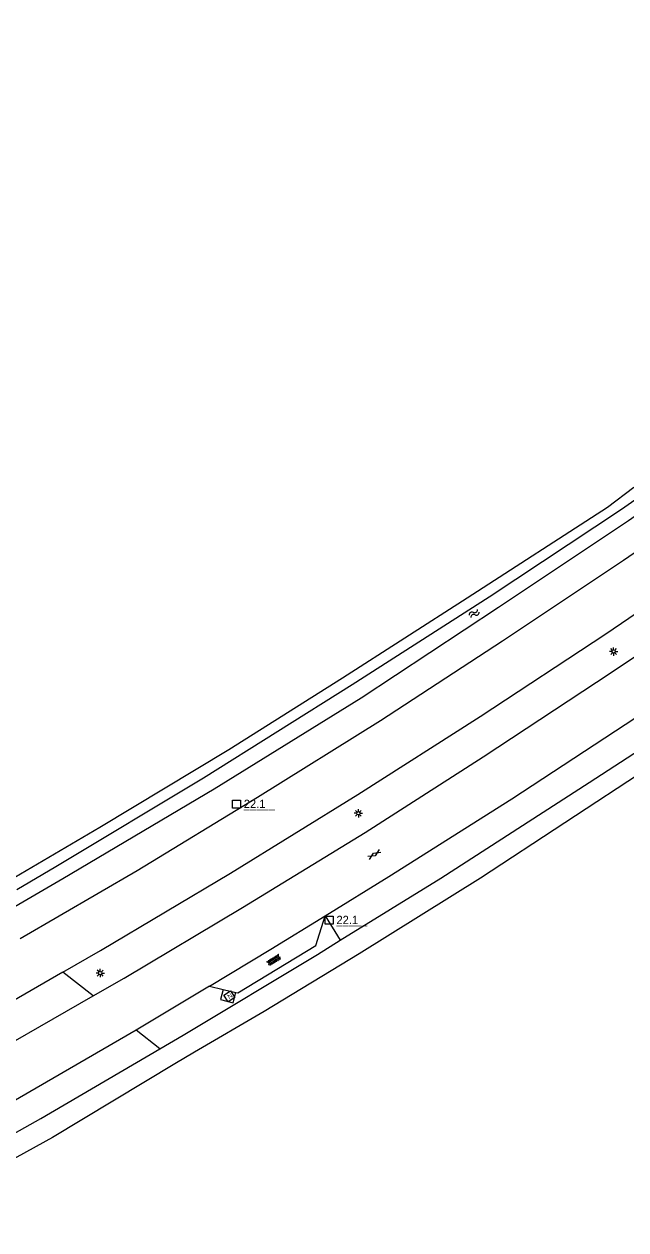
# Model space of a CAD drawing. Extents: x 124000 to 129000, y 395500 to 397503.
# Drawn here: x 125568.1 to 125658.6, y 397318.7 to 397500 of the extents above; entities that cross this region are included whole.
import ezdxf

# ---------------------------------------------------------------- set-up
doc = ezdxf.new("R2010")
doc.units = 0
for name, color, linetype in [('gg-knt-verharding', 7, 'Continuous'), ('gg-kntw-bovenkant insteek waterloop', 7, 'Continuous'), ('gt-anno-nummer hm paal', 7, 'Continuous'), ('gt-grn-groengrens', 7, 'Continuous'), ('gt-symb-gesloten verharding', 7, 'Continuous'), ('gt-symb-hm paal', 7, 'Continuous'), ('gt-symb-lichtmast', 7, 'Continuous'), ('gt-symb-nortonput', 7, 'Continuous'), ('gt-symb-overige verharding', 7, 'Continuous'), ('gt-symb-watersymbool', 7, 'Continuous'), ('gx-grn-maaiveld', 7, 'Continuous')]:
    doc.layers.add(name, color=color, linetype=linetype)

# ---------------------------------------------------------------- blocks, each defined once
blk = doc.blocks.new('gt0-GESVH1')
at = {"layer": 'gt-symb-gesloten verharding'}
for p, q in [((-0.99, -0.26), (0.01, 0.24)), ((0.01, -0.26), (-0.99, 0.24)), ((0.01, 0.24), (1.01, -0.26)), ((1.01, 0.24), (0.01, -0.26))]:
    blk.add_line(p, q, dxfattribs=at)
blk = doc.blocks.new('gt0-WA')
at = {"layer": 'gt-symb-watersymbool'}
for centre, start, end in [((-0.32, 0.02), 28.0725, 151.9275), ((0.43, 0.42), 208.0725, 331.9275), ((-0.32, -0.43), 28.0725, 151.9275), ((0.43, -0.03), 208.0725, 331.9275)]:
    blk.add_arc(centre, 0.425, start, end, dxfattribs=at)
blk = doc.blocks.new('gt0-LMAST')
at = {"layer": 'gt-symb-lichtmast'}
for p, q in [((-0.18, 0.17), (-0.45, 0.44)), ((-0.01, 0.25), (-0.01, 0.62)), ((0.17, 0.17), (0.44, 0.44)), ((-0.26, 0), (-0.63, 0)), ((-0.18, -0.18), (-0.45, -0.45)), ((-0.01, -0.25), (-0.01, -0.63)), ((0.44, -0.45), (0.17, -0.18)), ((0.24, 0), (0.62, 0))]:
    blk.add_line(p, q, dxfattribs=at)
blk.add_circle((-0.01, 0), 0.25, dxfattribs=at)
blk = doc.blocks.new('gt0-NPUT')
at = {"layer": 'gt-symb-nortonput'}
blk.add_lwpolyline([(-0.57, -0.61), (-0.57, 0.59), (0.63, 0.59), (0.63, -0.61)], close=True, dxfattribs=at)
blk.add_text('N', height=0.7, dxfattribs=at).set_placement((-0.22, -0.38))
blk = doc.blocks.new('gt0-OVH')
at = {"layer": 'gt-symb-overige verharding'}
for points in [[(-0.97, 0.3), (-0.97, 0.31), (-0.96, 0.32), (-0.97, 0.33), (-0.97, 0.34), (-0.98, 0.35), (-0.99, 0.35), (-1, 0.36), (-1.01, 0.35), (-1.02, 0.35), (-1.03, 0.34), (-1.03, 0.33), (-1.04, 0.32), (-1.03, 0.31), (-1.03, 0.3), (-1.02, 0.29), (-1.01, 0.29), (-1, 0.28), (-0.99, 0.29), (-0.98, 0.29)], [(-0.87, 0.11), (-0.87, 0.12), (-0.86, 0.13), (-0.87, 0.14), (-0.87, 0.15), (-0.88, 0.16), (-0.89, 0.16), (-0.9, 0.16), (-0.91, 0.16), (-0.92, 0.16), (-0.93, 0.15), (-0.93, 0.14), (-0.94, 0.13), (-0.93, 0.12), (-0.93, 0.11), (-0.92, 0.1), (-0.91, 0.09), (-0.9, 0.09), (-0.89, 0.09), (-0.88, 0.1)], [(-0.77, 0.3), (-0.77, 0.31), (-0.76, 0.32), (-0.77, 0.33), (-0.77, 0.34), (-0.78, 0.35), (-0.79, 0.35), (-0.8, 0.36), (-0.81, 0.35), (-0.82, 0.35), (-0.83, 0.34), (-0.83, 0.33), (-0.84, 0.32), (-0.83, 0.31), (-0.83, 0.3), (-0.82, 0.29), (-0.81, 0.29), (-0.8, 0.28), (-0.79, 0.29), (-0.78, 0.29)], [(-0.67, 0.11), (-0.67, 0.12), (-0.66, 0.13), (-0.67, 0.14), (-0.67, 0.15), (-0.68, 0.16), (-0.69, 0.16), (-0.7, 0.16), (-0.71, 0.16), (-0.72, 0.16), (-0.73, 0.15), (-0.73, 0.14), (-0.74, 0.13), (-0.73, 0.12), (-0.73, 0.11), (-0.72, 0.1), (-0.71, 0.09), (-0.7, 0.09), (-0.69, 0.09), (-0.68, 0.1)], [(-0.57, 0.3), (-0.57, 0.31), (-0.56, 0.32), (-0.57, 0.33), (-0.57, 0.34), (-0.58, 0.35), (-0.59, 0.35), (-0.6, 0.36), (-0.61, 0.35), (-0.62, 0.35), (-0.63, 0.34), (-0.63, 0.33), (-0.64, 0.32), (-0.63, 0.31), (-0.63, 0.3), (-0.62, 0.29), (-0.61, 0.29), (-0.6, 0.28), (-0.59, 0.29), (-0.58, 0.29)], [(-0.47, 0.11), (-0.47, 0.12), (-0.46, 0.13), (-0.47, 0.14), (-0.47, 0.15), (-0.48, 0.16), (-0.49, 0.16), (-0.5, 0.16), (-0.51, 0.16), (-0.52, 0.16), (-0.53, 0.15), (-0.53, 0.14), (-0.54, 0.13), (-0.53, 0.12), (-0.53, 0.11), (-0.52, 0.1), (-0.51, 0.09), (-0.5, 0.09), (-0.49, 0.09), (-0.48, 0.1)], [(-0.37, 0.3), (-0.37, 0.31), (-0.36, 0.32), (-0.37, 0.33), (-0.37, 0.34), (-0.38, 0.35), (-0.39, 0.35), (-0.4, 0.36), (-0.41, 0.35), (-0.42, 0.35), (-0.43, 0.34), (-0.43, 0.33), (-0.44, 0.32), (-0.43, 0.31), (-0.43, 0.3), (-0.42, 0.29), (-0.41, 0.29), (-0.4, 0.28), (-0.39, 0.29), (-0.38, 0.29)], [(-0.27, 0.11), (-0.27, 0.12), (-0.26, 0.13), (-0.27, 0.14), (-0.27, 0.15), (-0.28, 0.16), (-0.29, 0.16), (-0.3, 0.16), (-0.31, 0.16), (-0.32, 0.16), (-0.33, 0.15), (-0.33, 0.14), (-0.34, 0.13), (-0.33, 0.12), (-0.33, 0.11), (-0.32, 0.1), (-0.31, 0.09), (-0.3, 0.09), (-0.29, 0.09), (-0.28, 0.1)], [(-0.17, 0.3), (-0.17, 0.31), (-0.16, 0.32), (-0.17, 0.33), (-0.17, 0.34), (-0.18, 0.35), (-0.19, 0.35), (-0.2, 0.36), (-0.21, 0.35), (-0.22, 0.35), (-0.23, 0.34), (-0.23, 0.33), (-0.24, 0.32), (-0.23, 0.31), (-0.23, 0.3), (-0.22, 0.29), (-0.21, 0.29), (-0.2, 0.28), (-0.19, 0.29), (-0.18, 0.29)], [(-0.07, 0.11), (-0.07, 0.12), (-0.06, 0.13), (-0.07, 0.14), (-0.07, 0.15), (-0.08, 0.16), (-0.09, 0.16), (-0.1, 0.16), (-0.11, 0.16), (-0.12, 0.16), (-0.13, 0.15), (-0.13, 0.14), (-0.14, 0.13), (-0.13, 0.12), (-0.13, 0.11), (-0.12, 0.1), (-0.11, 0.09), (-0.1, 0.09), (-0.09, 0.09), (-0.08, 0.1)], [(0.03, 0.3), (0.03, 0.31), (0.04, 0.32), (0.03, 0.33), (0.03, 0.34), (0.02, 0.35), (0.01, 0.35), (0, 0.36), (-0.01, 0.35), (-0.02, 0.35), (-0.03, 0.34), (-0.03, 0.33), (-0.04, 0.32), (-0.03, 0.31), (-0.03, 0.3), (-0.02, 0.29), (-0.01, 0.29), (0, 0.28), (0.01, 0.29), (0.02, 0.29)], [(0.13, 0.11), (0.13, 0.12), (0.14, 0.13), (0.13, 0.14), (0.13, 0.15), (0.12, 0.16), (0.11, 0.16), (0.1, 0.16), (0.09, 0.16), (0.08, 0.16), (0.07, 0.15), (0.07, 0.14), (0.06, 0.13), (0.07, 0.12), (0.07, 0.11), (0.08, 0.1), (0.09, 0.09), (0.1, 0.09), (0.11, 0.09), (0.12, 0.1)], [(0.23, 0.3), (0.23, 0.31), (0.24, 0.32), (0.23, 0.33), (0.23, 0.34), (0.22, 0.35), (0.21, 0.35), (0.2, 0.36), (0.19, 0.35), (0.18, 0.35), (0.17, 0.34), (0.17, 0.33), (0.16, 0.32), (0.17, 0.31), (0.17, 0.3), (0.18, 0.29), (0.19, 0.29), (0.2, 0.28), (0.21, 0.29), (0.22, 0.29)], [(0.33, 0.11), (0.33, 0.12), (0.34, 0.13), (0.33, 0.14), (0.33, 0.15), (0.32, 0.16), (0.31, 0.16), (0.3, 0.16), (0.29, 0.16), (0.28, 0.16), (0.27, 0.15), (0.27, 0.14), (0.26, 0.13), (0.27, 0.12), (0.27, 0.11), (0.28, 0.1), (0.29, 0.09), (0.3, 0.09), (0.31, 0.09), (0.32, 0.1)], [(0.43, 0.3), (0.43, 0.31), (0.44, 0.32), (0.43, 0.33), (0.43, 0.34), (0.42, 0.35), (0.41, 0.35), (0.4, 0.36), (0.39, 0.35), (0.38, 0.35), (0.37, 0.34), (0.37, 0.33), (0.36, 0.32), (0.37, 0.31), (0.37, 0.3), (0.38, 0.29), (0.39, 0.29), (0.4, 0.28), (0.41, 0.29), (0.42, 0.29)], [(0.53, 0.11), (0.53, 0.12), (0.54, 0.13), (0.53, 0.14), (0.53, 0.15), (0.52, 0.16), (0.51, 0.16), (0.5, 0.16), (0.49, 0.16), (0.48, 0.16), (0.47, 0.15), (0.47, 0.14), (0.46, 0.13), (0.47, 0.12), (0.47, 0.11), (0.48, 0.1), (0.49, 0.09), (0.5, 0.09), (0.51, 0.09), (0.52, 0.1)], [(0.63, 0.3), (0.63, 0.31), (0.64, 0.32), (0.63, 0.33), (0.63, 0.34), (0.62, 0.35), (0.61, 0.35), (0.6, 0.36), (0.59, 0.35), (0.58, 0.35), (0.57, 0.34), (0.57, 0.33), (0.56, 0.32), (0.57, 0.31), (0.57, 0.3), (0.58, 0.29), (0.59, 0.29), (0.6, 0.28), (0.61, 0.29), (0.62, 0.29)], [(0.73, 0.11), (0.73, 0.12), (0.74, 0.13), (0.73, 0.14), (0.73, 0.15), (0.72, 0.16), (0.71, 0.16), (0.7, 0.16), (0.69, 0.16), (0.68, 0.16), (0.67, 0.15), (0.67, 0.14), (0.66, 0.13), (0.67, 0.12), (0.67, 0.11), (0.68, 0.1), (0.69, 0.09), (0.7, 0.09), (0.71, 0.09), (0.72, 0.1)], [(0.83, 0.3), (0.83, 0.31), (0.84, 0.32), (0.83, 0.33), (0.83, 0.34), (0.82, 0.35), (0.81, 0.35), (0.8, 0.36), (0.79, 0.35), (0.78, 0.35), (0.77, 0.34), (0.77, 0.33), (0.76, 0.32), (0.77, 0.31), (0.77, 0.3), (0.78, 0.29), (0.79, 0.29), (0.8, 0.28), (0.81, 0.29), (0.82, 0.29)], [(0.93, 0.11), (0.93, 0.12), (0.94, 0.13), (0.93, 0.14), (0.93, 0.15), (0.92, 0.16), (0.91, 0.16), (0.9, 0.16), (0.89, 0.16), (0.88, 0.16), (0.87, 0.15), (0.87, 0.14), (0.86, 0.13), (0.87, 0.12), (0.87, 0.11), (0.88, 0.1), (0.89, 0.09), (0.9, 0.09), (0.91, 0.09), (0.92, 0.1)], [(1.03, 0.3), (1.03, 0.31), (1.04, 0.32), (1.03, 0.33), (1.03, 0.34), (1.02, 0.35), (1.01, 0.35), (1, 0.36), (0.99, 0.35), (0.98, 0.35), (0.97, 0.34), (0.97, 0.33), (0.96, 0.32), (0.97, 0.31), (0.97, 0.3), (0.98, 0.29), (0.99, 0.29), (1, 0.28), (1.01, 0.29), (1.02, 0.29)], [(-0.97, -0.14), (-0.97, -0.13), (-0.96, -0.12), (-0.97, -0.11), (-0.97, -0.1), (-0.98, -0.09), (-0.99, -0.09), (-1, -0.08), (-1.01, -0.09), (-1.02, -0.09), (-1.03, -0.1), (-1.03, -0.11), (-1.04, -0.12), (-1.03, -0.13), (-1.03, -0.14), (-1.02, -0.15), (-1.01, -0.15), (-1, -0.16), (-0.99, -0.15), (-0.98, -0.15)], [(-0.87, -0.33), (-0.87, -0.32), (-0.86, -0.31), (-0.87, -0.3), (-0.87, -0.29), (-0.88, -0.28), (-0.89, -0.28), (-0.9, -0.28), (-0.91, -0.28), (-0.92, -0.28), (-0.93, -0.29), (-0.93, -0.3), (-0.94, -0.31), (-0.93, -0.32), (-0.93, -0.33), (-0.92, -0.34), (-0.91, -0.35), (-0.9, -0.35), (-0.89, -0.35), (-0.88, -0.34)], [(-0.77, -0.14), (-0.77, -0.13), (-0.76, -0.12), (-0.77, -0.11), (-0.77, -0.1), (-0.78, -0.09), (-0.79, -0.09), (-0.8, -0.08), (-0.81, -0.09), (-0.82, -0.09), (-0.83, -0.1), (-0.83, -0.11), (-0.84, -0.12), (-0.83, -0.13), (-0.83, -0.14), (-0.82, -0.15), (-0.81, -0.15), (-0.8, -0.16), (-0.79, -0.15), (-0.78, -0.15)], [(-0.67, -0.33), (-0.67, -0.32), (-0.66, -0.31), (-0.67, -0.3), (-0.67, -0.29), (-0.68, -0.28), (-0.69, -0.28), (-0.7, -0.28), (-0.71, -0.28), (-0.72, -0.28), (-0.73, -0.29), (-0.73, -0.3), (-0.74, -0.31), (-0.73, -0.32), (-0.73, -0.33), (-0.72, -0.34), (-0.71, -0.35), (-0.7, -0.35), (-0.69, -0.35), (-0.68, -0.34)], [(-0.57, -0.14), (-0.57, -0.13), (-0.56, -0.12), (-0.57, -0.11), (-0.57, -0.1), (-0.58, -0.09), (-0.59, -0.09), (-0.6, -0.08), (-0.61, -0.09), (-0.62, -0.09), (-0.63, -0.1), (-0.63, -0.11), (-0.64, -0.12), (-0.63, -0.13), (-0.63, -0.14), (-0.62, -0.15), (-0.61, -0.15), (-0.6, -0.16), (-0.59, -0.15), (-0.58, -0.15)], [(-0.47, -0.33), (-0.47, -0.32), (-0.46, -0.31), (-0.47, -0.3), (-0.47, -0.29), (-0.48, -0.28), (-0.49, -0.28), (-0.5, -0.28), (-0.51, -0.28), (-0.52, -0.28), (-0.53, -0.29), (-0.53, -0.3), (-0.54, -0.31), (-0.53, -0.32), (-0.53, -0.33), (-0.52, -0.34), (-0.51, -0.35), (-0.5, -0.35), (-0.49, -0.35), (-0.48, -0.34)], [(-0.37, -0.14), (-0.37, -0.13), (-0.36, -0.12), (-0.37, -0.11), (-0.37, -0.1), (-0.38, -0.09), (-0.39, -0.09), (-0.4, -0.08), (-0.41, -0.09), (-0.42, -0.09), (-0.43, -0.1), (-0.43, -0.11), (-0.44, -0.12), (-0.43, -0.13), (-0.43, -0.14), (-0.42, -0.15), (-0.41, -0.15), (-0.4, -0.16), (-0.39, -0.15), (-0.38, -0.15)], [(-0.27, -0.33), (-0.27, -0.32), (-0.26, -0.31), (-0.27, -0.3), (-0.27, -0.29), (-0.28, -0.28), (-0.29, -0.28), (-0.3, -0.28), (-0.31, -0.28), (-0.32, -0.28), (-0.33, -0.29), (-0.33, -0.3), (-0.34, -0.31), (-0.33, -0.32), (-0.33, -0.33), (-0.32, -0.34), (-0.31, -0.35), (-0.3, -0.35), (-0.29, -0.35), (-0.28, -0.34)], [(-0.17, -0.14), (-0.17, -0.13), (-0.16, -0.12), (-0.17, -0.11), (-0.17, -0.1), (-0.18, -0.09), (-0.19, -0.09), (-0.2, -0.08), (-0.21, -0.09), (-0.22, -0.09), (-0.23, -0.1), (-0.23, -0.11), (-0.24, -0.12), (-0.23, -0.13), (-0.23, -0.14), (-0.22, -0.15), (-0.21, -0.15), (-0.2, -0.16), (-0.19, -0.15), (-0.18, -0.15)], [(-0.07, -0.33), (-0.07, -0.32), (-0.06, -0.31), (-0.07, -0.3), (-0.07, -0.29), (-0.08, -0.28), (-0.09, -0.28), (-0.1, -0.28), (-0.11, -0.28), (-0.12, -0.28), (-0.13, -0.29), (-0.13, -0.3), (-0.14, -0.31), (-0.13, -0.32), (-0.13, -0.33), (-0.12, -0.34), (-0.11, -0.35), (-0.1, -0.35), (-0.09, -0.35), (-0.08, -0.34)], [(0.03, -0.14), (0.03, -0.13), (0.04, -0.12), (0.03, -0.11), (0.03, -0.1), (0.02, -0.09), (0.01, -0.09), (0, -0.08), (-0.01, -0.09), (-0.02, -0.09), (-0.03, -0.1), (-0.03, -0.11), (-0.04, -0.12), (-0.03, -0.13), (-0.03, -0.14), (-0.02, -0.15), (-0.01, -0.15), (0, -0.16), (0.01, -0.15), (0.02, -0.15)], [(0.13, -0.33), (0.13, -0.32), (0.14, -0.31), (0.13, -0.3), (0.13, -0.29), (0.12, -0.28), (0.11, -0.28), (0.1, -0.28), (0.09, -0.28), (0.08, -0.28), (0.07, -0.29), (0.07, -0.3), (0.06, -0.31), (0.07, -0.32), (0.07, -0.33), (0.08, -0.34), (0.09, -0.35), (0.1, -0.35), (0.11, -0.35), (0.12, -0.34)], [(0.23, -0.14), (0.23, -0.13), (0.24, -0.12), (0.23, -0.11), (0.23, -0.1), (0.22, -0.09), (0.21, -0.09), (0.2, -0.08), (0.19, -0.09), (0.18, -0.09), (0.17, -0.1), (0.17, -0.11), (0.16, -0.12), (0.17, -0.13), (0.17, -0.14), (0.18, -0.15), (0.19, -0.15), (0.2, -0.16), (0.21, -0.15), (0.22, -0.15)], [(0.33, -0.33), (0.33, -0.32), (0.34, -0.31), (0.33, -0.3), (0.33, -0.29), (0.32, -0.28), (0.31, -0.28), (0.3, -0.28), (0.29, -0.28), (0.28, -0.28), (0.27, -0.29), (0.27, -0.3), (0.26, -0.31), (0.27, -0.32), (0.27, -0.33), (0.28, -0.34), (0.29, -0.35), (0.3, -0.35), (0.31, -0.35), (0.32, -0.34)], [(0.43, -0.14), (0.43, -0.13), (0.44, -0.12), (0.43, -0.11), (0.43, -0.1), (0.42, -0.09), (0.41, -0.09), (0.4, -0.08), (0.39, -0.09), (0.38, -0.09), (0.37, -0.1), (0.37, -0.11), (0.36, -0.12), (0.37, -0.13), (0.37, -0.14), (0.38, -0.15), (0.39, -0.15), (0.4, -0.16), (0.41, -0.15), (0.42, -0.15)], [(0.53, -0.33), (0.53, -0.32), (0.54, -0.31), (0.53, -0.3), (0.53, -0.29), (0.52, -0.28), (0.51, -0.28), (0.5, -0.28), (0.49, -0.28), (0.48, -0.28), (0.47, -0.29), (0.47, -0.3), (0.46, -0.31), (0.47, -0.32), (0.47, -0.33), (0.48, -0.34), (0.49, -0.35), (0.5, -0.35), (0.51, -0.35), (0.52, -0.34)], [(0.63, -0.14), (0.63, -0.13), (0.64, -0.12), (0.63, -0.11), (0.63, -0.1), (0.62, -0.09), (0.61, -0.09), (0.6, -0.08), (0.59, -0.09), (0.58, -0.09), (0.57, -0.1), (0.57, -0.11), (0.56, -0.12), (0.57, -0.13), (0.57, -0.14), (0.58, -0.15), (0.59, -0.15), (0.6, -0.16), (0.61, -0.15), (0.62, -0.15)], [(0.73, -0.33), (0.73, -0.32), (0.74, -0.31), (0.73, -0.3), (0.73, -0.29), (0.72, -0.28), (0.71, -0.28), (0.7, -0.28), (0.69, -0.28), (0.68, -0.28), (0.67, -0.29), (0.67, -0.3), (0.66, -0.31), (0.67, -0.32), (0.67, -0.33), (0.68, -0.34), (0.69, -0.35), (0.7, -0.35), (0.71, -0.35), (0.72, -0.34)], [(0.83, -0.14), (0.83, -0.13), (0.84, -0.12), (0.83, -0.11), (0.83, -0.1), (0.82, -0.09), (0.81, -0.09), (0.8, -0.08), (0.79, -0.09), (0.78, -0.09), (0.77, -0.1), (0.77, -0.11), (0.76, -0.12), (0.77, -0.13), (0.77, -0.14), (0.78, -0.15), (0.79, -0.15), (0.8, -0.16), (0.81, -0.15), (0.82, -0.15)], [(0.93, -0.33), (0.93, -0.32), (0.94, -0.31), (0.93, -0.3), (0.93, -0.29), (0.92, -0.28), (0.91, -0.28), (0.9, -0.28), (0.89, -0.28), (0.88, -0.28), (0.87, -0.29), (0.87, -0.3), (0.86, -0.31), (0.87, -0.32), (0.87, -0.33), (0.88, -0.34), (0.89, -0.35), (0.9, -0.35), (0.91, -0.35), (0.92, -0.34)], [(1.03, -0.14), (1.03, -0.13), (1.04, -0.12), (1.03, -0.11), (1.03, -0.1), (1.02, -0.09), (1.01, -0.09), (1, -0.08), (0.99, -0.09), (0.98, -0.09), (0.97, -0.1), (0.97, -0.11), (0.96, -0.12), (0.97, -0.13), (0.97, -0.14), (0.98, -0.15), (0.99, -0.15), (1, -0.16), (1.01, -0.15), (1.02, -0.15)]]:
    blk.add_lwpolyline(points, close=True, dxfattribs=at)
blk = doc.blocks.new('gt0-HMpaal')
at = {"layer": 'gt-symb-hm paal'}
blk.add_lwpolyline([(-0.6, 0.6), (0.6, 0.6), (0.6, -0.6), (-0.6, -0.6)], close=True, dxfattribs=at)

msp = doc.modelspace()

# ---------------------------------------------------------------- linework, layer by layer
at = {"layer": 'gg-knt-verharding'}
for p, q in [((125578.47, 397353.88), (125583.13, 397356.54)), ((125596.01, 397355.35), (125584.98, 397348.73)), ((125596.01, 397355.35), (125598.04, 397354.86)), ((125598.04, 397354.86), (125599.97, 397354.41))]:
    msp.add_line(p, q, dxfattribs=at)
for points in [[(125567.52, 397362.52), (125585.13, 397372.73), (125603.21, 397383.76), (125621.72, 397395.29), (125640.08, 397407.25), (125658.28, 397419.4), (125675.77, 397431.43), (125694.33, 397444.57), (125712.08, 397457.47), (125728.99, 397470.42), (125745.9, 397483.45), (125762.67, 397496.87), (125766.45, 397500)], [(125573.94, 397357.46), (125579.57, 397360.72), (125599.17, 397372.32), (125618.29, 397384.18), (125636.73, 397395.91), (125655.62, 397408.31), (125674.01, 397420.84), (125692.24, 397433.69), (125710.23, 397446.65), (125728.22, 397460.2), (125744.63, 397472.69), (125762.31, 397486.7), (125767.49, 397490.92), (125778.49, 397500)], [(125583.13, 397356.54), (125600.95, 397367.2), (125619.39, 397378.46), (125637.14, 397389.82), (125656.43, 397402.52), (125673.97, 397414.31), (125692.08, 397426.92), (125712.09, 397441.37), (125731.39, 397455.83), (125752.04, 397471.99), (125751.89, 397472.25), (125752.89, 397473.03), (125764.6, 397482.34), (125776.3, 397491.82), (125786.16, 397500)], [(125613.39, 397365.92), (125622.99, 397371.84), (125641.49, 397383.49), (125660.14, 397395.75), (125678.4, 397408.04), (125695.96, 397420.31), (125710.6, 397430.95), (125726.59, 397442.7), (125740.87, 397453.38), (125758.05, 397466.72), (125776.34, 397481.34), (125793.68, 397496.08), (125798.24, 397500)], [(125596.01, 397355.35), (125605.21, 397360.89), (125613.39, 397365.92)], [(125599.97, 397354.41), (125600.25, 397354.34), (125611.98, 397361.45), (125613.39, 397365.92)], [(125573.94, 397357.46), (125556.13, 397347.16), (125534.72, 397335.38), (125512.12, 397323.32), (125490.61, 397312.41), (125467.71, 397301.33), (125445.04, 397290.75), (125422.65, 397280.78), (125402.74, 397272.26), (125381.07, 397263.36), (125360.35, 397255.08), (125343.85, 397248.87), (125325.72, 397242.33), (125304.81, 397235.06), (125281.95, 397227.25), (125261.44, 397219.96), (125217.98, 397203.36), (125198.47, 397195.39)], [(125598.04, 397354.86), (125597.64, 397353.32), (125599.57, 397352.85), (125599.97, 397354.41)], [(125420.35, 397273.93), (125425.18, 397275.99), (125447.4, 397285.97), (125470.02, 397296.51), (125492.88, 397307.68), (125514.57, 397318.71), (125536.92, 397330.6), (125558.73, 397342.59), (125578.47, 397353.88)], [(125584.98, 397348.73), (125564.89, 397337.09), (125545.39, 397326.35), (125525.61, 397315.8), (125508.51, 397306.86), (125487.88, 397296.53), (125467.04, 397286.59), (125445.4, 397276.62), (125423.85, 397267.02)]]:
    msp.add_lwpolyline(points, dxfattribs=at)
at = {"layer": 'gg-kntw-bovenkant insteek waterloop'}
for points in [[(125563.65, 397365.58), (125573.92, 397371.52), (125596.7, 397385.02), (125618.83, 397398.69), (125639.49, 397412.34), (125659.03, 397425.34), (125680.13, 397440.12), (125700.39, 397454.72), (125720.23, 397469.47), (125739.7, 397484.43), (125758.84, 397499.72), (125759.17, 397500)], [(125567, 397369.9), (125572.87, 397373.36), (125595.1, 397386.69), (125617.47, 397400.69), (125638.05, 397413.88), (125657.98, 397427.08), (125678.77, 397441.64), (125698.79, 397456.18), (125718.86, 397471.13), (125738.34, 397486.12), (125755.69, 397500)], [(125615.65, 397362.24), (125630.8, 397371.61), (125653.09, 397385.96), (125670.25, 397397.11), (125688.64, 397409.96), (125708.14, 397423.8), (125727.27, 397437.58), (125744.12, 397450.29), (125760.92, 397463.56), (125775.85, 397475.75), (125787.46, 397485.46), (125793.6, 397490.22), (125794.37, 397489.94)], [(125662.15, 397388.22), (125636.76, 397371.6), (125618.51, 397360.2), (125604.23, 397351.53), (125593.71, 397345.43), (125590.79, 397343.67)], [(125588.54, 397345.93), (125592.04, 397347.98), (125612.22, 397360.12), (125615.65, 397362.24)], [(125539.23, 397317.94), (125550.6, 397324.21), (125570.6, 397335.46), (125588.54, 397345.93)], [(125590.79, 397343.67), (125572.37, 397332.61), (125552.33, 397321.59), (125532.64, 397311.29), (125517.82, 397303.76), (125486.83, 397288.02), (125473.03, 397281.39), (125454.9, 397272.8), (125445.58, 397268.58), (125421.67, 397258.05), (125405.46, 397251.51), (125400.1, 397249.35)]]:
    msp.add_lwpolyline(points, dxfattribs=at)
at = {"layer": 'gt-grn-groengrens'}
for p, q in [((125613.39, 397365.92), (125615.65, 397362.24)), ((125578.47, 397353.88), (125573.94, 397357.46)), ((125588.54, 397345.93), (125584.98, 397348.73))]:
    msp.add_line(p, q, dxfattribs=at)
at = {"layer": 'gx-grn-maaiveld'}
msp.add_lwpolyline([(125564.99, 397370.71), (125579.5, 397379.25), (125598.92, 397390.95), (125615.99, 397401.69), (125634.73, 397413.73), (125655.86, 397427.35), (125659.85, 397430.4)], dxfattribs=at)

# ---------------------------------------------------------------- block references
at = {"layer": 'gt-symb-gesloten verharding', "rotation": 32.211897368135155}
msp.add_blockref('gt0-GESVH1', (125620.78, 397375.16), dxfattribs=at)
at = {"layer": 'gt-symb-hm paal'}
for p in [(125600.07, 397382.73), (125614.01, 397365.29)]:
    msp.add_blockref('gt0-HMpaal', p, dxfattribs=at)
at = {"layer": 'gt-symb-lichtmast'}
for p in [(125656.8, 397405.67), (125618.39, 397381.34), (125579.55, 397357.32)]:
    msp.add_blockref('gt0-LMAST', p, dxfattribs=at)
at = {"layer": 'gt-symb-nortonput', "rotation": 33.99203971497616}
msp.add_blockref('gt0-NPUT', (125598.94, 397353.81), dxfattribs=at)
at = {"layer": 'gt-symb-overige verharding', "rotation": 31.79891282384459}
msp.add_blockref('gt0-OVH', (125605.68, 397359.26), dxfattribs=at)
at = {"layer": 'gt-symb-watersymbool', "rotation": -146.54839854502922}
msp.add_blockref('gt0-WA', (125635.86, 397411.39), dxfattribs=at)

# ---------------------------------------------------------------- texts
at = {"layer": 'gt-anno-nummer hm paal'}
for p in [(125601.15, 397382.13), (125615.09, 397364.68)]:
    msp.add_text('22.1', height=1.25, dxfattribs=at).set_placement(p)
at = {"layer": 'gt-symb-hm paal'}
for p in [(125601.15, 397382.13), (125615.09, 397364.68)]:
    msp.add_text('_____', height=1.25, dxfattribs=at).set_placement(p)

doc.saveas('drawing.dxf')
